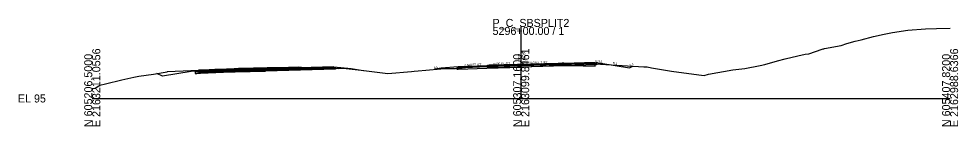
# Model space of a CAD drawing. Extents: x -26 to 1303, y -10 to 12033.
# Drawn here: x -25.7 to 302.8, y 8490.3 to 8527.8 of the extents above; entities that cross this region are included whole.
import ezdxf

# ---------------------------------------------------------------- set-up
doc = ezdxf.new("R2010")
doc.units = 0
for name, color, linetype in [('RD_GPK_XS_Cell', 7, 'Continuous'), ('RD_XS_Base', 7, 'Continuous'), ('RD_XS_ExGround', 7, 'Continuous'), ('RD_XS_ExPaveRet', 7, 'Continuous'), ('RD_XS_Greenside', 7, 'Continuous'), ('RD_XS_Pave', 7, 'Continuous'), ('RD_XS_PaveOvlay_CP', 7, 'Continuous'), ('RD_XS_TieSlope', 7, 'Continuous'), ('RD_XS_TX_Elev_EX', 7, 'Continuous'), ('RD_XS_TX_Elev_PR', 7, 'Continuous'), ('RD_XS_TX_ShdSlope', 7, 'Continuous'), ('RD_XS_TX_Slope', 7, 'Continuous')]:
    doc.layers.add(name, color=color, linetype=linetype)

msp = doc.modelspace()

# ---------------------------------------------------------------- linework, layer by layer
at = {"layer": 'RD_GPK_XS_Cell'}
for p, q in [((150, 8500), (150, 8525)), ((0, 8500), (150, 8500)), ((150, 8500), (300, 8500))]:
    msp.add_line(p, q, dxfattribs=at)
at = {"layer": 'RD_XS_Base'}
for p, q in [((36.1, 8509.25), (36.04, 8509.25)), ((36.04, 8509.25), (36.04, 8508.8)), ((36.54, 8509.27), (36.1, 8509.25)), ((37.84, 8509.32), (36.54, 8509.27)), ((48.54, 8509.75), (37.84, 8509.32)), ((37.84, 8508.82), (48.54, 8509.25)), ((49.99, 8509.79), (48.54, 8509.75)), ((48.54, 8509.25), (49.99, 8509.29)), ((60.54, 8510.06), (49.99, 8509.79)), ((49.99, 8509.29), (60.54, 8509.56)), ((60.54, 8510.06), (85.04, 8510.7)), ((60.54, 8509.56), (60.54, 8510.22)), ((60.54, 8510.22), (60.54, 8510.22)), ((60.54, 8510.22), (60.54, 8510.22)), ((60.54, 8510.22), (60.54, 8510.06)), ((85.04, 8510.2), (60.54, 8509.56)), ((60.54, 8510.06), (60.54, 8510.06)), ((60.54, 8509.56), (60.54, 8510.06)), ((60.54, 8510.06), (60.54, 8510.06)), ((60.54, 8510.06), (60.54, 8510.06)), ((60.54, 8509.56), (60.54, 8509.56)), ((84.54, 8510.68), (84.54, 8510.68)), ((84.54, 8510.68), (84.54, 8510.68)), ((84.54, 8510.68), (84.54, 8510.68)), ((84.54, 8510.18), (84.54, 8510.18)), ((84.54, 8510.18), (84.54, 8510.18)), ((85.04, 8510.7), (85.04, 8510.2)), ((85.04, 8510.66), (85.04, 8510.66)), ((128, 8510.74), (127.5, 8510.72)), ((127.5, 8510.72), (127.5, 8510.72)), ((127.5, 8510.72), (127.5, 8510.22)), ((127.5, 8510.22), (128, 8510.24)), ((138, 8511.14), (128, 8510.74)), ((128, 8510.74), (128, 8510.74)), ((128, 8510.24), (138, 8510.64)), ((128, 8510.24), (128, 8510.24)), ((136, 8511.06), (136, 8511.06)), ((136, 8510.56), (136, 8510.56)), ((150, 8511.48), (138, 8511.14)), ((138, 8510.64), (150, 8510.98)), ((150, 8511.48), (175.87, 8512.2)), ((176.37, 8511.72), (150, 8510.98)), ((150, 8510.98), (150, 8511.64)), ((150, 8511.64), (150, 8511.64)), ((150, 8511.64), (150, 8511.64)), ((150, 8511.64), (150, 8511.48)), ((150, 8511.48), (150, 8511.48)), ((150, 8510.98), (150, 8511.48)), ((150, 8511.48), (150, 8511.48)), ((150, 8511.48), (150, 8511.48)), ((150, 8510.98), (150, 8510.98)), ((162, 8511.82), (162, 8511.82)), ((162, 8511.82), (162, 8511.82)), ((162, 8511.32), (162, 8511.32)), ((162, 8511.32), (162, 8511.32)), ((175.87, 8512.2), (175.87, 8512.2)), ((176.37, 8512.22), (176.37, 8511.72)), ((176.37, 8512.18), (176.37, 8512.18)), ((36.04, 8508.8), (36.04, 8508.75)), ((36.04, 8508.75), (36.1, 8508.75)), ((36.1, 8508.75), (36.54, 8508.77)), ((36.54, 8508.77), (37.84, 8508.82))]:
    msp.add_line(p, q, dxfattribs=at)
at = {"layer": 'RD_XS_ExGround'}
msp.add_lwpolyline([(0, 8503.54), (1.01, 8503.57), (2.25, 8504.38), (2.65, 8504.66), (4.65, 8505.14), (10.4, 8506.5), (14.51, 8507.42), (16.28, 8507.74), (21.38, 8508.5), (26.21, 8509.36), (26.31, 8509.38), (34.46, 8509.73), (37.11, 8509.84), (38.94, 8509.94), (44.26, 8510.13), (50.3, 8510.41), (51.36, 8510.44), (54.19, 8510.5), (54.21, 8510.5), (55.18, 8510.51), (56.36, 8510.55), (56.93, 8510.59), (59.58, 8510.64), (61.21, 8510.67), (69.5, 8510.87), (72.27, 8510.93), (73.12, 8510.92), (80.75, 8510.81), (81.52, 8510.77), (83.51, 8510.65), (86.08, 8510.51), (88.14, 8510.54), (88.78, 8510.46), (94.05, 8509.91), (103.41, 8508.73), (111.63, 8509.42), (112.57, 8509.5), (114.03, 8509.7), (116.6, 8509.92), (121.94, 8510.41), (122.55, 8510.43), (127.01, 8510.53), (135.29, 8511.3), (136.95, 8511.45), (138.25, 8511.57), (138.77, 8511.58), (139.3, 8511.59), (153.51, 8511.95), (162.96, 8512.27), (164.29, 8512.31), (164.93, 8512.31), (171.69, 8512.21), (175.92, 8512.09), (192.91, 8511.07), (194.07, 8511.01), (195.63, 8510.73), (202.56, 8509.5), (212.13, 8508.31), (214.04, 8508.06), (215.56, 8508.44), (224.01, 8509.97), (228.23, 8510.47), (233.55, 8511.51), (235.22, 8511.92), (239.59, 8513.11), (242.29, 8513.88), (246.8, 8514.89), (249.33, 8515.5), (250.56, 8515.58), (255.22, 8517.2), (255.64, 8517.31), (255.79, 8517.36), (256.13, 8517.43), (261.86, 8518.51), (263.87, 8519.19), (266.8, 8519.98), (268.9, 8520.53), (273.23, 8521.68), (276.95, 8522.5), (279.87, 8523), (285.27, 8523.92), (291.44, 8524.32), (295.19, 8524.49), (300, 8524.53)], dxfattribs=at)
at = {"layer": 'RD_XS_ExPaveRet'}
for points in [[(171.69, 8512.21), (164.93, 8512.31), (164.93, 8512.31), (164.93, 8512.31), (164.29, 8512.31), (162.96, 8512.27), (162.96, 8512.27), (153.51, 8511.95), (153.51, 8511.95), (139.3, 8511.59), (139.3, 8511.59), (138.77, 8511.58), (138.25, 8511.57), (138.25, 8511.57), (138.25, 8511.57), (138.25, 8510.82), (138.25, 8510.82), (138.77, 8510.83), (139.3, 8510.84), (139.3, 8510.84), (153.51, 8511.2), (153.51, 8511.2), (162.96, 8511.52), (162.96, 8511.52), (164.29, 8511.56), (164.93, 8511.56), (164.93, 8511.56), (164.93, 8511.56), (171.69, 8511.46), (171.69, 8511.46), (175.92, 8511.34), (175.92, 8512.09), (175.92, 8512.09), (171.69, 8512.21), (171.69, 8512.21)], [(171.69, 8512.21), (164.93, 8512.31), (164.29, 8512.31), (162.96, 8512.27), (153.51, 8511.95), (139.3, 8511.59), (138.77, 8511.58), (138.25, 8511.57), (138.25, 8511.57), (138.25, 8510.82), (138.25, 8510.82), (138.77, 8510.83), (139.3, 8510.84), (153.51, 8511.2), (162.96, 8511.52), (164.29, 8511.56), (164.93, 8511.56), (171.69, 8511.46), (175.92, 8511.34), (175.92, 8512.09), (171.69, 8512.21)], [(69.53, 8510.87), (69.5, 8510.87), (68.68, 8510.85), (61.21, 8510.67), (61.13, 8510.67), (59.58, 8510.64), (59.36, 8510.63), (56.93, 8510.59), (56.43, 8510.55), (56.36, 8510.55), (55.29, 8510.52), (55.18, 8510.51), (54.35, 8510.5), (54.21, 8510.5), (54.19, 8510.5), (54.19, 8510.5), (53.99, 8510.49), (51.36, 8510.44), (51.18, 8510.44), (50.3, 8510.41), (49.68, 8510.38), (44.26, 8510.13), (42.88, 8510.08), (38.94, 8509.94), (38.39, 8509.91), (37.11, 8509.84), (37.11, 8509.66), (37.11, 8509.09), (38.39, 8509.16), (38.94, 8509.19), (42.88, 8509.33), (44.26, 8509.38), (49.68, 8509.63), (50.3, 8509.66), (51.18, 8509.69), (51.36, 8509.69), (53.99, 8509.74), (54.19, 8509.75), (54.19, 8509.75), (54.21, 8509.75), (54.35, 8509.75), (55.18, 8509.76), (55.29, 8509.77), (56.36, 8509.8), (56.43, 8509.8), (56.93, 8509.84), (59.36, 8509.88), (59.58, 8509.89), (61.13, 8509.92), (61.21, 8509.92), (68.68, 8510.1), (69.5, 8510.12), (69.53, 8510.12), (72.27, 8510.18), (72.27, 8510.19), (72.27, 8510.93), (69.53, 8510.87)], [(69.53, 8510.87), (69.5, 8510.87), (68.68, 8510.85), (61.21, 8510.67), (61.13, 8510.67), (59.58, 8510.64), (59.36, 8510.63), (56.93, 8510.59), (56.43, 8510.55), (56.36, 8510.55), (55.29, 8510.52), (55.18, 8510.51), (54.35, 8510.5), (54.21, 8510.5), (54.19, 8510.5), (54.19, 8510.5), (53.99, 8510.49), (51.36, 8510.44), (51.18, 8510.44), (50.3, 8510.41), (49.68, 8510.38), (44.26, 8510.13), (42.88, 8510.08), (38.94, 8509.94), (38.39, 8509.91), (37.11, 8509.84), (37.11, 8509.66), (37.11, 8509.09), (38.39, 8509.16), (38.94, 8509.19), (42.88, 8509.33), (44.26, 8509.38), (49.68, 8509.63), (50.3, 8509.66), (51.18, 8509.69), (51.36, 8509.69), (53.99, 8509.74), (54.19, 8509.75), (54.19, 8509.75), (54.21, 8509.75), (54.35, 8509.75), (55.18, 8509.76), (55.29, 8509.77), (56.36, 8509.8), (56.43, 8509.8), (56.93, 8509.84), (59.36, 8509.88), (59.58, 8509.89), (61.13, 8509.92), (61.21, 8509.92), (68.68, 8510.1), (69.5, 8510.12), (69.53, 8510.12), (72.27, 8510.18), (72.27, 8510.19), (72.27, 8510.93), (69.53, 8510.87)]]:
    msp.add_lwpolyline(points, dxfattribs=at)
at = {"layer": 'RD_XS_Greenside'}
for p, q in [((177.87, 8512.36), (187.87, 8510.7)), ((34.54, 8509.43), (24.54, 8507.76)), ((90.54, 8510.52), (94.77, 8509.82)), ((122, 8510.58), (119.8, 8510.22)), ((187.87, 8510.7), (189.08, 8511.3)), ((24.54, 8507.76), (22.61, 8508.73))]:
    msp.add_line(p, q, dxfattribs=at)
at = {"layer": 'RD_XS_Pave'}
for p, q in [((175.87, 8512.52), (150, 8511.8)), ((175.87, 8512.36), (150, 8511.64)), ((150, 8511.64), (175.87, 8512.36)), ((175.87, 8512.36), (175.87, 8512.52)), ((175.87, 8512.52), (175.87, 8512.52)), ((175.87, 8512.2), (175.87, 8512.36)), ((175.87, 8512.36), (175.87, 8512.36)), ((37.84, 8509.64), (36.54, 8509.59)), ((36.54, 8509.59), (36.54, 8509.45)), ((36.54, 8509.43), (37.84, 8509.48)), ((37.84, 8509.48), (36.54, 8509.43)), ((36.54, 8509.45), (36.54, 8509.43)), ((36.54, 8509.43), (36.54, 8509.29)), ((36.54, 8509.27), (37.84, 8509.32)), ((36.54, 8509.29), (36.54, 8509.27)), ((48.54, 8510.07), (37.84, 8509.64)), ((37.84, 8509.48), (48.54, 8509.91)), ((48.54, 8509.91), (37.84, 8509.48)), ((37.84, 8509.32), (48.54, 8509.75)), ((49.99, 8510.1), (48.54, 8510.07)), ((48.54, 8509.91), (49.99, 8509.95)), ((49.99, 8509.95), (48.54, 8509.91)), ((48.54, 8509.75), (49.99, 8509.79)), ((60.54, 8510.38), (49.99, 8510.1)), ((49.99, 8509.95), (60.54, 8510.22)), ((60.54, 8510.22), (49.99, 8509.95)), ((49.99, 8509.79), (60.54, 8510.06)), ((84.54, 8511), (60.54, 8510.38)), ((84.54, 8510.84), (60.54, 8510.22)), ((60.54, 8510.22), (84.54, 8510.84)), ((60.54, 8510.06), (84.54, 8510.68)), ((60.54, 8510.38), (60.54, 8510.38)), ((60.54, 8510.22), (60.54, 8510.22)), ((60.54, 8510.22), (60.54, 8510.22)), ((60.54, 8510.22), (60.54, 8510.06)), ((60.54, 8510.22), (60.54, 8510.22)), ((60.54, 8510.06), (60.54, 8510.22)), ((60.54, 8510.22), (60.54, 8510.22)), ((60.54, 8510.22), (60.54, 8510.22)), ((60.54, 8510.06), (60.54, 8510.06)), ((60.54, 8510.06), (60.54, 8510.06)), ((84.54, 8510.84), (84.54, 8511)), ((84.54, 8511), (84.54, 8511)), ((84.54, 8511), (84.54, 8511)), ((84.54, 8511), (84.54, 8511)), ((84.54, 8510.68), (84.54, 8510.84)), ((84.54, 8510.84), (84.54, 8510.84)), ((84.54, 8510.84), (84.54, 8510.84)), ((84.54, 8510.84), (84.54, 8510.84)), ((84.54, 8510.84), (84.54, 8510.84)), ((84.54, 8510.84), (84.54, 8510.84)), ((84.54, 8510.68), (84.54, 8510.68)), ((84.54, 8510.68), (84.54, 8510.68)), ((138, 8511.46), (128, 8511.06)), ((128, 8510.9), (138, 8511.3)), ((138, 8511.3), (128, 8510.9)), ((128, 8510.74), (138, 8511.14)), ((128, 8511.06), (128, 8511.06)), ((128, 8511.06), (128, 8510.9)), ((128, 8510.9), (128, 8510.9)), ((128, 8510.9), (128, 8510.74)), ((136, 8511.38), (136, 8511.38)), ((136, 8511.22), (136, 8511.22)), ((136, 8511.22), (136, 8511.22)), ((136, 8511.06), (136, 8511.06)), ((150, 8511.8), (138, 8511.46)), ((138, 8511.3), (150, 8511.64)), ((150, 8511.64), (138, 8511.3)), ((138, 8511.14), (150, 8511.48)), ((150, 8511.48), (176.37, 8512.22)), ((150, 8511.8), (150, 8511.8)), ((150, 8511.64), (150, 8511.64)), ((150, 8511.64), (150, 8511.64)), ((150, 8511.64), (150, 8511.48)), ((150, 8511.64), (150, 8511.64)), ((150, 8511.48), (150, 8511.64)), ((150, 8511.64), (150, 8511.64)), ((150, 8511.64), (150, 8511.64)), ((150, 8511.48), (150, 8511.48)), ((150, 8511.48), (150, 8511.48)), ((162, 8512.13), (162, 8512.13)), ((162, 8512.13), (162, 8512.13)), ((162, 8511.98), (162, 8511.98)), ((162, 8511.98), (162, 8511.98)), ((162, 8511.98), (162, 8511.98)), ((162, 8511.98), (162, 8511.98)), ((162, 8511.82), (162, 8511.82)), ((162, 8511.82), (162, 8511.82))]:
    msp.add_line(p, q, dxfattribs=at)
at = {"layer": 'RD_XS_PaveOvlay_CP'}
for p, q in [((175.87, 8512.52), (150, 8511.8)), ((37.84, 8509.64), (36.54, 8509.59)), ((48.54, 8510.07), (37.84, 8509.64)), ((49.99, 8510.1), (48.54, 8510.07)), ((60.54, 8510.38), (49.99, 8510.1)), ((84.54, 8511), (60.54, 8510.38)), ((60.54, 8510.38), (60.54, 8510.38)), ((84.54, 8511), (84.54, 8511)), ((84.54, 8511), (84.54, 8511)), ((138, 8511.46), (128, 8511.06)), ((136, 8511.38), (136, 8511.38)), ((150, 8511.8), (138, 8511.46)), ((150, 8511.8), (150, 8511.8)), ((162, 8512.13), (162, 8512.13)), ((162, 8512.13), (162, 8512.13))]:
    msp.add_line(p, q, dxfattribs=at)
at = {"layer": 'RD_XS_TieSlope'}
for p, q in [((175.87, 8512.52), (177.87, 8512.36)), ((36.54, 8509.59), (34.54, 8509.43)), ((84.54, 8511), (90.54, 8510.52)), ((128, 8511.06), (122, 8510.58))]:
    msp.add_line(p, q, dxfattribs=at)

# ---------------------------------------------------------------- texts
at = {"layer": 'RD_GPK_XS_Cell'}
for s, p in [('P_C_SBSPLIT2', (140, 8525)), ('5296+00.00 / 1', (140, 8522.2)), ('EL 95', (-26, 8498.6))]:
    msp.add_text(s, height=2.8, dxfattribs=at).set_placement(p)
for s, p in [('E 2163211.0556', (2.8, 8490)), ('E 2163099.8461', (152.8, 8490)), ('E 2162988.6366', (302.8, 8490)), ('N 605206.5000', (0, 8490)), ('N 605307.1600', (150, 8490)), ('N 605407.8200', (300, 8490))]:
    msp.add_text(s, height=2.8, rotation=90, dxfattribs=at).set_placement(p)
at = {"layer": 'RD_XS_TX_Elev_EX'}
msp.add_text('106.86', height=0.6, rotation=90, dxfattribs=at).set_placement((149.53, 8513.07))
at = {"layer": 'RD_XS_TX_Elev_PR'}
msp.add_text('106.80', height=1, rotation=90, dxfattribs=at).set_placement((151.49, 8512.58))
at = {"layer": 'RD_XS_TX_ShdSlope'}
msp.add_text('12.5:1', height=0.75, rotation=355.4261, dxfattribs=at).set_placement((175.56, 8512.73))
at = {"layer": 'RD_XS_TX_Slope'}
for s, rotation, p in [('0.030 FT./FT.', 1.7184, (140.11, 8511.68)), ('0.030 FT./FT.', 1.7184, (153.16, 8512.06)), ('6:1', 350.5358, (182, 8512.05)), ('2:1', 26.5651, (188.13, 8511.24)), ('6:1', 9.4623, (119.47, 8510.47)), ('0.040 FT./FT.', 2.2906, (130.15, 8511.27))]:
    msp.add_text(s, height=0.75, rotation=rotation, dxfattribs=at).set_placement(p)

doc.saveas('drawing.dxf')
